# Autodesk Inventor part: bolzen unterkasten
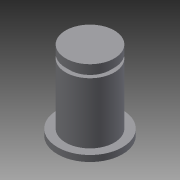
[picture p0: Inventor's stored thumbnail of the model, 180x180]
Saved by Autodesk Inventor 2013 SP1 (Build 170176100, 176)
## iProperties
Created: 2012-11
Part Number: bolzen unterkasten
Material: Allgemein
Document SubType Name: Modeling
Designer: s0536599
Density: 1 g/cm^3
Author: s0536599
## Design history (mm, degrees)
sketch "Skizze1"
  geometry: L1 (0, 0)-(6, 0); L2 (6, 0)-(6, 15); L3 (6, 15)-(5, 15); L4 (5, 15)-(5, 16); L5 (5, 16)-(6, 16); L6 (6, 16)-(6, 18); L7 (6, 18)-(0, 18); L8 (6, 0)-(8, 0); L9 (8, 0)-(8, -1.5); L10 (8, -1.5)-(0, -1.5); L11 (0, 18)-(0, -1.5); L12 (0, -5.4)-(0, 21.9) reference; L13 (9.6, 0)-(-1.6, 0) reference
  constraints: 22 end point, 5 parallel, 5 perpendicular, 1 horizontal
  dimensions: "d0" = 6 distance of L1.start L1.end; "d1" = 15 distance of L1.end L2.end; "d2" = 1 distance of L2.end L3.end; "d3" = 1 distance of L3.end L4.end; "d4" = 1 distance of L4.end L5.end; "d5" = 2 distance of L5.end L6.end; "d6" = 2 distance of L1.end L8.end; "d7" = 1.5 distance of L8.end L9.end
revolve "Umdrehung1" sketch "Skizze1" stored, may be unused: angle "d8" = 90 deg
node "Volumenkörper1"
